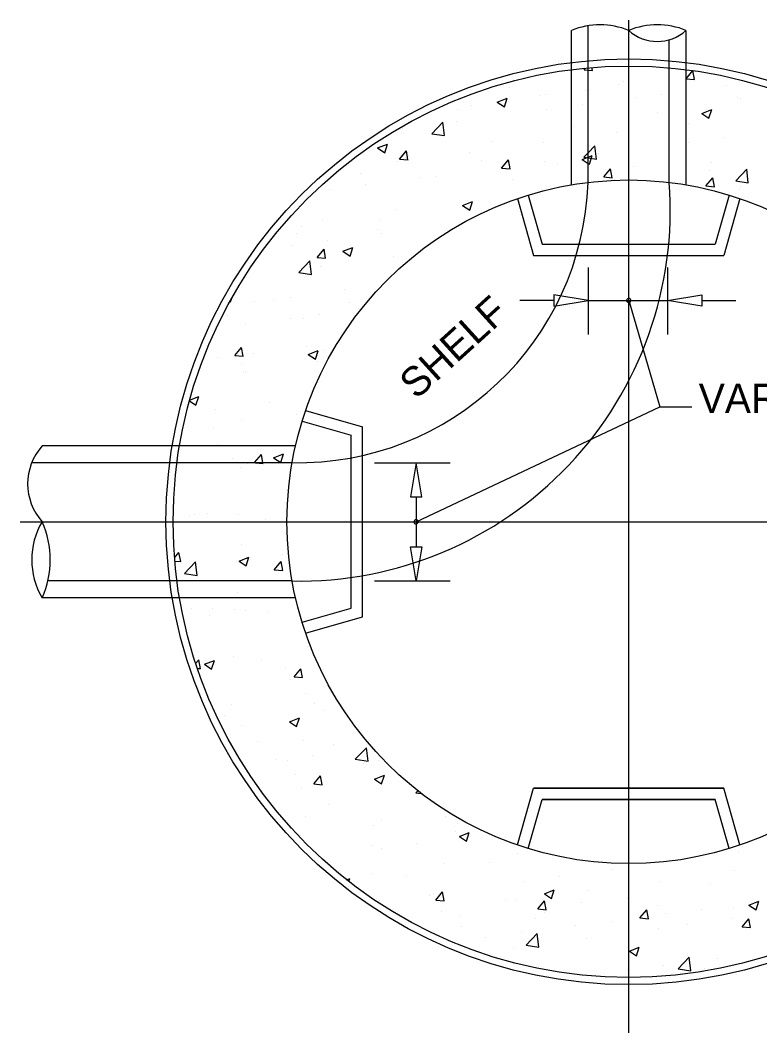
# Model space of a CAD drawing. Extents: x 6712067 to 6713867, y 1867712 to 1869162.
# Drawn here: x 6713498 to 6713649.4, y 1867917.6 to 1868124.8 of the extents above; entities that cross this region are included whole.
import ezdxf

# ---------------------------------------------------------------- set-up
doc = ezdxf.new("R2010")
doc.units = 0
for name, color, linetype in [('G-MARK', 7, 'Continuous'), ('G-TEXT', 7, 'Continuous'), ('Misc CnstDet(22)', 7, 'Continuous')]:
    doc.layers.add(name, color=color, linetype=linetype)

msp = doc.modelspace()

# ---------------------------------------------------------------- linework, layer by layer
at = {"layer": 'G-MARK'}
for p, q in [((6713614.28, 1868074.21), (6713614.28, 1868060.48)), ((6713630.55, 1868074.21), (6713630.55, 1868060.48)), ((6713607.29, 1868067.47), (6713600.29, 1868067.47)), ((6713614.28, 1868067.47), (6713630.55, 1868067.47)), ((6713622.6, 1868067.47), (6713628.98, 1868045.69)), ((6713637.54, 1868067.47), (6713644.54, 1868067.47)), ((6713570.53, 1868034.25), (6713586.06, 1868034.25)), ((6713579.06, 1868027.26), (6713579.06, 1868017.05)), ((6713570.53, 1868010.05), (6713586.06, 1868010.05))]:
    msp.add_line(p, q, dxfattribs=at)
msp.add_lwpolyline([(6713579.06, 1868022.15), (6713628.98, 1868045.69), (6713635.55, 1868045.69)], dxfattribs=at)
at = {"layer": 'G-TEXT'}
for points in [[(6713607.29, 1868068.64), (6713607.29, 1868066.31), (6713614.28, 1868067.47)], [(6713637.54, 1868068.64), (6713637.54, 1868066.31), (6713630.55, 1868067.47)], [(6713577.9, 1868027.26), (6713580.23, 1868027.26), (6713579.06, 1868034.25)], [(6713577.9, 1868017.05), (6713580.23, 1868017.05), (6713579.06, 1868010.05)]]:
    msp.add_lwpolyline(points, close=True, dxfattribs=at)
at = {"layer": 'Misc CnstDet(22)'}
for p, q in [((6713622.6, 1867917.57), (6713622.6, 1868124.81)), ((6713610.86, 1868116.15), (6713610.86, 1868122.72)), ((6713614.28, 1868091.62), (6713614.28, 1868123.68)), ((6713634.33, 1868116.15), (6713634.33, 1868122.72)), ((6713630.91, 1868091.62), (6713630.91, 1868120.8)), ((6713610.86, 1868091.11), (6713610.86, 1868116.26)), ((6713613.45, 1868114.65), (6713613.74, 1868115)), ((6713613.45, 1868114.65), (6713614.28, 1868114.58)), ((6713614.28, 1868114.58), (6713615.19, 1868114.5)), ((6713615.19, 1868114.5), (6713615.08, 1868115.12)), ((6713634.33, 1868091.11), (6713634.33, 1868116.12)), ((6713634.35, 1868112.82), (6713635.75, 1868114.5)), ((6713636.1, 1868112.66), (6713635.75, 1868114.49)), ((6713621.51, 1868112.28), (6713621.51, 1868112.28)), ((6713634.35, 1868112.82), (6713636.1, 1868112.67)), ((6713635.16, 1868113.48), (6713635.16, 1868113.48)), ((6713598.24, 1868111.01), (6713598.24, 1868111.01)), ((6713613.8, 1868110.36), (6713613.8, 1868110.36)), ((6713620.43, 1868111.61), (6713620.43, 1868111.61)), ((6713642.56, 1868111.37), (6713642.56, 1868111.37)), ((6713595.68, 1868108.06), (6713597.72, 1868108.85)), ((6713595.68, 1868108.06), (6713597.14, 1868107.08)), ((6713597.14, 1868107.08), (6713597.72, 1868108.84)), ((6713604.52, 1868109.37), (6713604.52, 1868109.37)), ((6713605.47, 1868109.55), (6713605.47, 1868109.55)), ((6713624.15, 1868108.94), (6713624.15, 1868108.94)), ((6713629.36, 1868109.7), (6713629.36, 1868109.7)), ((6713644.91, 1868109.05), (6713644.91, 1868109.05)), ((6713645.5, 1868108.79), (6713645.5, 1868108.79)), ((6713587.52, 1868106.44), (6713587.52, 1868106.44)), ((6713590.33, 1868107.37), (6713590.33, 1868107.37)), ((6713605.81, 1868106.52), (6713605.81, 1868106.52)), ((6713613.11, 1868107.49), (6713613.11, 1868107.49)), ((6713628.5, 1868105.88), (6713628.5, 1868105.88)), ((6713637.58, 1868105.73), (6713639.62, 1868106.51)), ((6713639.03, 1868104.74), (6713639.62, 1868106.51)), ((6713582.29, 1868101.59), (6713584.56, 1868103.95)), ((6713584.88, 1868101.19), (6713584.56, 1868103.95)), ((6713587.41, 1868104.1), (6713587.41, 1868104.1)), ((6713634.81, 1868103.77), (6713634.81, 1868103.77)), ((6713637.58, 1868105.73), (6713639.03, 1868104.76)), ((6713576.37, 1868102.66), (6713576.37, 1868102.66)), ((6713611.51, 1868102.97), (6713611.51, 1868102.97)), ((6713620.09, 1868101.9), (6713620.09, 1868101.9)), ((6713582.29, 1868101.59), (6713584.88, 1868101.19)), ((6713594.51, 1868100.05), (6713594.51, 1868100.05)), ((6713605.11, 1868099.86), (6713605.11, 1868099.86)), ((6713634.89, 1868099.87), (6713634.89, 1868099.87)), ((6713642.19, 1868100.83), (6713642.19, 1868100.83)), ((6713571.19, 1868098.66), (6713573.23, 1868099.44)), ((6713571.19, 1868098.66), (6713572.65, 1868097.69)), ((6713572.65, 1868097.69), (6713573.23, 1868099.44)), ((6713575.68, 1868096.39), (6713577.08, 1868098.06)), ((6713577.41, 1868096.23), (6713577.08, 1868098.05)), ((6713589.98, 1868097.66), (6713589.98, 1868097.66)), ((6713613.4, 1868096.77), (6713614.28, 1868097.7)), ((6713614.28, 1868097.7), (6713615.67, 1868099.13)), ((6713615.98, 1868096.37), (6713615.66, 1868099.13)), ((6713575.25, 1868095.8), (6713575.25, 1868095.8)), ((6713575.68, 1868096.39), (6713577.42, 1868096.23)), ((6713577, 1868096.78), (6713577, 1868096.78)), ((6713577.5, 1868097.12), (6713577.5, 1868097.12)), ((6713592.56, 1868096.11), (6713592.56, 1868096.11)), ((6713596.59, 1868094.55), (6713597.99, 1868096.23)), ((6713598.32, 1868094.4), (6713597.99, 1868096.23)), ((6713605.45, 1868095.99), (6713605.45, 1868095.99)), ((6713613.09, 1868096.33), (6713614.28, 1868096.79)), ((6713613.09, 1868096.33), (6713614.28, 1868095.52)), ((6713613.4, 1868096.77), (6713614.28, 1868096.63)), ((6713614.28, 1868096.79), (6713615.12, 1868097.11)), ((6713614.28, 1868096.63), (6713615.99, 1868096.37)), ((6713614.28, 1868095.52), (6713614.54, 1868095.35)), ((6713614.54, 1868095.35), (6713615.12, 1868097.11)), ((6713616.49, 1868097.45), (6713616.49, 1868097.45)), ((6713639.63, 1868095.68), (6713639.63, 1868095.68)), ((6713567.59, 1868093.52), (6713567.59, 1868093.52)), ((6713596.59, 1868094.55), (6713598.32, 1868094.4)), ((6713598.15, 1868095.04), (6713598.15, 1868095.04)), ((6713608.12, 1868095.46), (6713608.12, 1868095.46)), ((6713617.49, 1868092.73), (6713618.9, 1868094.4)), ((6713619.23, 1868092.57), (6713618.9, 1868094.4)), ((6713623.68, 1868094.81), (6713623.68, 1868094.81)), ((6713634.46, 1868094.06), (6713634.46, 1868094.06)), ((6713639.24, 1868094.15), (6713639.24, 1868094.15)), ((6713644.5, 1868091.94), (6713646.77, 1868094.31)), ((6713647.09, 1868091.53), (6713646.77, 1868094.3)), ((6713579.74, 1868092.6), (6713579.74, 1868092.6)), ((6713583.15, 1868092.87), (6713583.15, 1868092.87)), ((6713598.71, 1868092.2), (6713598.71, 1868092.2)), ((6713617.49, 1868092.73), (6713619.23, 1868092.58)), ((6713619.73, 1868092.2), (6713619.73, 1868092.2)), ((6713622.64, 1868092.76), (6713622.64, 1868092.76)), ((6713638.39, 1868090.89), (6713639.81, 1868092.57)), ((6713640.14, 1868090.74), (6713639.81, 1868092.57)), ((6713644.5, 1868091.94), (6713647.09, 1868091.53)), ((6713561.4, 1868090.19), (6713561.4, 1868090.19)), ((6713568.7, 1868091.16), (6713568.7, 1868091.16)), ((6713604.77, 1868090.15), (6713604.77, 1868090.15)), ((6713638.39, 1868090.89), (6713640.14, 1868090.74)), ((6713645.38, 1868090.23), (6713645.38, 1868090.23)), ((6713645.56, 1868090.79), (6713645.56, 1868090.79)), ((6713588.59, 1868086.92), (6713590.63, 1868087.71)), ((6713589.62, 1868087.97), (6713589.62, 1868087.97)), ((6713590.05, 1868085.95), (6713590.63, 1868087.71)), ((6713599.81, 1868088.29), (6713603.14, 1868076.66)), ((6713599.81, 1868088.29), (6713603.14, 1868076.66)), ((6713602.04, 1868089.01), (6713604.9, 1868078.99)), ((6713643.16, 1868089.01), (6713640.3, 1868078.99)), ((6713645.38, 1868088.29), (6713642.06, 1868076.66)), ((6713574.9, 1868086.1), (6713574.9, 1868086.1)), ((6713588.59, 1868086.92), (6713590.05, 1868085.95)), ((6713588.63, 1868086.93), (6713588.63, 1868086.93)), ((6713559.93, 1868084.04), (6713559.93, 1868084.04)), ((6713571.64, 1868084.01), (6713571.64, 1868084.01)), ((6713554.64, 1868081.09), (6713554.64, 1868081.09)), ((6713555.64, 1868082.62), (6713555.64, 1868082.62)), ((6713571.2, 1868081.96), (6713571.2, 1868081.96)), ((6713572.07, 1868081.11), (6713572.07, 1868081.11)), ((6713561.03, 1868079.66), (6713561.03, 1868079.66)), ((6713604.9, 1868078.99), (6713640.3, 1868078.99)), ((6713553.74, 1868078.69), (6713553.74, 1868078.69)), ((6713558.81, 1868076.28), (6713560.22, 1868077.96)), ((6713560.55, 1868076.13), (6713560.22, 1868077.96)), ((6713564.1, 1868077.52), (6713566.14, 1868078.31)), ((6713564.1, 1868077.52), (6713565.56, 1868076.55)), ((6713565.56, 1868076.55), (6713566.14, 1868078.3)), ((6713555.04, 1868073.2), (6713557.32, 1868075.56)), ((6713557.64, 1868072.79), (6713557.32, 1868075.56)), ((6713558.81, 1868076.28), (6713560.55, 1868076.13)), ((6713574.54, 1868076.39), (6713574.54, 1868076.39)), ((6713603.14, 1868076.66), (6713642.06, 1868076.66)), ((6713614.28, 1868076.66), (6713614.28, 1868076.66)), ((6713630.55, 1868076.66), (6713630.55, 1868076.66)), ((6713555.04, 1868073.2), (6713557.64, 1868072.79)), ((6713559.58, 1868074.34), (6713559.58, 1868074.34)), ((6713544.44, 1868072.15), (6713544.44, 1868072.15)), ((6713564.4, 1868069.62), (6713564.4, 1868069.62)), ((6713540.94, 1868067.23), (6713541.05, 1868067.15)), ((6713541.05, 1868067.15), (6713541.32, 1868067.91)), ((6713546.06, 1868067.19), (6713546.06, 1868067.19)), ((6713549.96, 1868067.72), (6713549.96, 1868067.72)), ((6713553.36, 1868068.16), (6713553.36, 1868068.16)), ((6713565.52, 1868067.07), (6713565.52, 1868067.07)), ((6713630.55, 1868067.47), (6713630.55, 1868067.47)), ((6713540.55, 1868064.46), (6713540.55, 1868064.46)), ((6713559.22, 1868064.64), (6713559.22, 1868064.64)), ((6713544.08, 1868062.45), (6713544.08, 1868062.45)), ((6713553.44, 1868063.69), (6713553.44, 1868063.69)), ((6713556.11, 1868063.81), (6713556.11, 1868063.81)), ((6713541.95, 1868056.19), (6713543.35, 1868057.86)), ((6713541.95, 1868056.19), (6713543.69, 1868056.04)), ((6713543.69, 1868056.04), (6713543.35, 1868057.86)), ((6713545.69, 1868056.66), (6713545.69, 1868056.66)), ((6713556.73, 1868058.12), (6713556.73, 1868058.12)), ((6713557.01, 1868056.38), (6713559.05, 1868057.18)), ((6713557.01, 1868056.38), (6713558.46, 1868055.41)), ((6713558.46, 1868055.41), (6713559.05, 1868057.16)), ((6713560.41, 1868057.3), (6713560.41, 1868057.3)), ((6713538.39, 1868055.71), (6713538.39, 1868055.71)), ((6713543.42, 1868054.39), (6713543.42, 1868054.39)), ((6713558.88, 1868054.93), (6713558.88, 1868054.93)), ((6713543.73, 1868052.75), (6713543.73, 1868052.75)), ((6713544.16, 1868052.91), (6713544.16, 1868052.91)), ((6713532.67, 1868046.89), (6713533.96, 1868046.01)), ((6713532.71, 1868047.07), (6713534.56, 1868047.77)), ((6713533.96, 1868046.01), (6713534.56, 1868047.77)), ((6713549.07, 1868046.62), (6713549.07, 1868046.62)), ((6713538.03, 1868045.17), (6713538.03, 1868045.17)), ((6713554.55, 1868044.18), (6713554.55, 1868044.18)), ((6713556.46, 1868044.93), (6713568.09, 1868041.6)), ((6713543.37, 1868043.05), (6713543.37, 1868043.05)), ((6713555.73, 1868042.72), (6713565.76, 1868039.85)), ((6713568.09, 1868002.69), (6713568.09, 1868041.6)), ((6713537.55, 1868041.26), (6713537.55, 1868041.26)), ((6713565.76, 1868004.46), (6713565.76, 1868039.85)), ((6713529.14, 1868037.68), (6713502.5, 1868037.68)), ((6713554.39, 1868037.68), (6713529.14, 1868037.68)), ((6713538.48, 1868038.01), (6713538.48, 1868038.01)), ((6713545.99, 1868034.27), (6713547.4, 1868035.95)), ((6713547.71, 1868034.25), (6713547.4, 1868035.93)), ((6713549.91, 1868035.25), (6713551.96, 1868036.04)), ((6713551.36, 1868034.27), (6713551.96, 1868036.04)), ((6713554.05, 1868037.36), (6713554.05, 1868037.36)), ((6713553.69, 1868034.25), (6713500.38, 1868034.25)), ((6713530.36, 1868033.67), (6713530.36, 1868033.67)), ((6713541.4, 1868035.12), (6713541.4, 1868035.12)), ((6713543.03, 1868033.34), (6713543.03, 1868033.34)), ((6713544.64, 1868034.1), (6713544.64, 1868034.1)), ((6713545.99, 1868034.27), (6713546.17, 1868034.25)), ((6713546.17, 1868034.25), (6713547.73, 1868034.11)), ((6713547.73, 1868034.11), (6713547.71, 1868034.25)), ((6713549.91, 1868035.25), (6713551.37, 1868034.27)), ((6713568.09, 1868034.25), (6713568.09, 1868034.25)), ((6713552.14, 1868026.05), (6713552.14, 1868026.05)), ((6713532.69, 1868023.2), (6713532.69, 1868023.2)), ((6713533.73, 1868023.63), (6713533.73, 1868023.63)), ((6713536.35, 1868023.87), (6713536.35, 1868023.87)), ((6713542.67, 1868023.63), (6713542.67, 1868023.63)), ((6713498.03, 1868022.15), (6713728.02, 1868022.15)), ((6713548.25, 1868022.54), (6713548.25, 1868022.54)), ((6713543.34, 1868017.47), (6713543.34, 1868017.47)), ((6713529.61, 1868014.75), (6713530.53, 1868015.84)), ((6713530.88, 1868014.01), (6713530.53, 1868015.84)), ((6713542.82, 1868014.12), (6713544.86, 1868014.9)), ((6713544.27, 1868013.13), (6713544.86, 1868014.9)), ((6713551.76, 1868015.52), (6713551.76, 1868015.52)), ((6713529.67, 1868014.12), (6713530.88, 1868014.01)), ((6713531.67, 1868011.58), (6713533.93, 1868013.95)), ((6713534.25, 1868011.18), (6713533.93, 1868013.95)), ((6713542.32, 1868013.93), (6713542.32, 1868013.93)), ((6713542.82, 1868014.12), (6713544.28, 1868013.13)), ((6713544.46, 1868014.55), (6713544.46, 1868014.55)), ((6713550.04, 1868012.34), (6713551.44, 1868014.01)), ((6713551.77, 1868012.19), (6713551.44, 1868014.01)), ((6713531.67, 1868011.58), (6713534.25, 1868011.18)), ((6713550.04, 1868012.34), (6713551.78, 1868012.19)), ((6713553.69, 1868010.04), (6713503.67, 1868010.04)), ((6713568.09, 1868010.05), (6713568.09, 1868010.05)), ((6713579.06, 1868010.05), (6713579.06, 1868010.05)), ((6713529.14, 1868006.62), (6713502.5, 1868006.62)), ((6713554.39, 1868006.62), (6713529.14, 1868006.62)), ((6713542.57, 1868007.65), (6713542.57, 1868007.65)), ((6713533.16, 1868004.39), (6713533.16, 1868004.39)), ((6713537.46, 1868004.35), (6713537.46, 1868004.35)), ((6713555.73, 1868001.59), (6713565.76, 1868004.46)), ((6713536.8, 1868003.06), (6713536.8, 1868003.06)), ((6713541.96, 1868004.23), (6713541.96, 1868004.23)), ((6713544.1, 1868004.02), (6713544.1, 1868004.02)), ((6713548.72, 1868003.72), (6713548.72, 1868003.72)), ((6713556.46, 1867999.36), (6713568.09, 1868002.69)), ((6713556.74, 1867996.71), (6713556.74, 1867996.71)), ((6713541.61, 1867994.53), (6713541.61, 1867994.53)), ((6713547.47, 1867993.98), (6713547.47, 1867993.98)), ((6713533.94, 1867993.16), (6713534.58, 1867993.92)), ((6713534.27, 1867992.15), (6713534.92, 1867992.1)), ((6713534.92, 1867992.08), (6713534.58, 1867993.92)), ((6713535.73, 1867992.98), (6713537.77, 1867993.76)), ((6713535.73, 1867992.98), (6713537.19, 1867992)), ((6713536.43, 1867992.52), (6713536.43, 1867992.52)), ((6713536.77, 1867992.83), (6713536.77, 1867992.83)), ((6713537.18, 1867991.99), (6713537.77, 1867993.76)), ((6713552.34, 1867992.16), (6713552.34, 1867992.16)), ((6713554.08, 1867990.42), (6713555.49, 1867992.08)), ((6713555.82, 1867990.26), (6713555.49, 1867992.08)), ((6713553.27, 1867989.88), (6713553.27, 1867989.88)), ((6713554.08, 1867990.42), (6713555.82, 1867990.26)), ((6713536.27, 1867986.95), (6713536.27, 1867986.95)), ((6713556.39, 1867987.01), (6713556.39, 1867987.01)), ((6713541.25, 1867984.82), (6713541.25, 1867984.82)), ((6713558.21, 1867984.9), (6713558.21, 1867984.9)), ((6713539.8, 1867982.48), (6713539.8, 1867982.48)), ((6713553.13, 1867981.24), (6713555.17, 1867982.02)), ((6713554.59, 1867980.26), (6713555.17, 1867982.02)), ((6713560.24, 1867983.48), (6713560.24, 1867983.48)), ((6713543.25, 1867980.56), (6713543.25, 1867980.56)), ((6713553.13, 1867981.24), (6713554.59, 1867980.26)), ((6713546.66, 1867977.27), (6713546.66, 1867977.27)), ((6713556.03, 1867977.3), (6713556.03, 1867977.3)), ((6713562.22, 1867976.61), (6713562.22, 1867976.61)), ((6713566.63, 1867973.54), (6713568.91, 1867975.9)), ((6713568.88, 1867975.82), (6713568.88, 1867975.82)), ((6713569.23, 1867973.14), (6713568.91, 1867975.9)), ((6713550.55, 1867973.4), (6713550.55, 1867973.4)), ((6713552.81, 1867973.36), (6713552.81, 1867973.36)), ((6713557.84, 1867974.37), (6713557.84, 1867974.37)), ((6713566.63, 1867973.54), (6713569.23, 1867973.14)), ((6713571.39, 1867973.27), (6713571.39, 1867973.27)), ((6713568.37, 1867972.7), (6713568.37, 1867972.7)), ((6713554.38, 1867970.36), (6713554.38, 1867970.36)), ((6713558.13, 1867968.49), (6713559.53, 1867970.16)), ((6713559.86, 1867968.33), (6713559.53, 1867970.16)), ((6713570.53, 1867969.5), (6713572.57, 1867970.29)), ((6713570.53, 1867969.5), (6713571.98, 1867968.52)), ((6713570.65, 1867969.65), (6713570.65, 1867969.65)), ((6713571.98, 1867968.52), (6713572.57, 1867970.28)), ((6713555.69, 1867967.61), (6713555.69, 1867967.61)), ((6713558.13, 1867968.49), (6713559.86, 1867968.34)), ((6713579.03, 1867966.66), (6713579.41, 1867967.11)), ((6713599.81, 1867956), (6713603.14, 1867967.64)), ((6713599.81, 1867956), (6713603.14, 1867967.64)), ((6713603.14, 1867967.64), (6713642.06, 1867967.64)), ((6713642.06, 1867967.64), (6713603.14, 1867967.64)), ((6713645.38, 1867956), (6713642.06, 1867967.64)), ((6713645.38, 1867956), (6713642.06, 1867967.64)), ((6713579.03, 1867966.66), (6713580.12, 1867966.56)), ((6713579.61, 1867966.74), (6713579.61, 1867966.74)), ((6713602.04, 1867955.28), (6713604.9, 1867965.31)), ((6713602.04, 1867955.28), (6713604.9, 1867965.31)), ((6713604.9, 1867965.31), (6713640.3, 1867965.31)), ((6713640.3, 1867965.31), (6713604.9, 1867965.31)), ((6713643.16, 1867955.28), (6713640.3, 1867965.31)), ((6713643.16, 1867955.28), (6713640.3, 1867965.31)), ((6713561.21, 1867964.32), (6713561.21, 1867964.32)), ((6713556.42, 1867961.8), (6713556.42, 1867961.8)), ((6713571.98, 1867961.14), (6713571.98, 1867961.14)), ((6713585.02, 1867961.81), (6713585.02, 1867961.81)), ((6713570.3, 1867959.95), (6713570.3, 1867959.95)), ((6713587.18, 1867958.8), (6713587.18, 1867958.8)), ((6713587.54, 1867960.48), (6713587.54, 1867960.48)), ((6713555.33, 1867957.9), (6713555.33, 1867957.9)), ((6713587.93, 1867957.77), (6713589.97, 1867958.55)), ((6713587.93, 1867957.77), (6713589.38, 1867956.8)), ((6713589.38, 1867956.78), (6713589.97, 1867958.55)), ((6713590.29, 1867957.67), (6713590.29, 1867957.67)), ((6713570.18, 1867955.89), (6713570.18, 1867955.89)), ((6713571.95, 1867955.25), (6713571.95, 1867955.25)), ((6713579.25, 1867956.21), (6713579.25, 1867956.21)), ((6713599.8, 1867954.29), (6713599.8, 1867954.29)), ((6713637.77, 1867953.43), (6713637.77, 1867953.43)), ((6713645.07, 1867954.39), (6713645.07, 1867954.39)), ((6713584.66, 1867952.11), (6713584.66, 1867952.11)), ((6713594.17, 1867952.4), (6713594.17, 1867952.4)), ((6713619.37, 1867951), (6713619.37, 1867951)), ((6713644.28, 1867950.7), (6713644.28, 1867950.7)), ((6713564.84, 1867948.9), (6713565.48, 1867949.15)), ((6713565.28, 1867948.56), (6713565.48, 1867949.15)), ((6713569.94, 1867950.24), (6713569.94, 1867950.24)), ((6713577.16, 1867949.49), (6713577.16, 1867949.49)), ((6713601.03, 1867948.59), (6713601.03, 1867948.59)), ((6713608.33, 1867949.55), (6713608.33, 1867949.55)), ((6713629.13, 1867948.51), (6713629.13, 1867948.51)), ((6713583.08, 1867944.73), (6713584.48, 1867946.41)), ((6713584.82, 1867944.58), (6713584.48, 1867946.41)), ((6713605.33, 1867946.03), (6713607.37, 1867946.81)), ((6713606.78, 1867945.06), (6713607.37, 1867946.81)), ((6713614.41, 1867946.65), (6713614.41, 1867946.65)), ((6713639.29, 1867948.04), (6713639.29, 1867948.04)), ((6713571.58, 1867944.71), (6713571.58, 1867944.71)), ((6713581.86, 1867945.58), (6713581.86, 1867945.58)), ((6713582.62, 1867946.17), (6713582.62, 1867946.17)), ((6713583.08, 1867944.73), (6713584.82, 1867944.58)), ((6713597.42, 1867944.93), (6713597.42, 1867944.93)), ((6713599.44, 1867944.6), (6713599.44, 1867944.6)), ((6713603.99, 1867942.91), (6713605.39, 1867944.58)), ((6713605.33, 1867946.03), (6713606.78, 1867945.06)), ((6713605.72, 1867942.75), (6713605.39, 1867944.57)), ((6713612.99, 1867944.27), (6713612.99, 1867944.27)), ((6713622.29, 1867945.12), (6713622.29, 1867945.12)), ((6713647.22, 1867943.7), (6713649.26, 1867944.48)), ((6713648.45, 1867944.34), (6713648.45, 1867944.34)), ((6713648.67, 1867942.71), (6713649.26, 1867944.48)), ((6713584.31, 1867942.4), (6713584.31, 1867942.4)), ((6713603.99, 1867942.91), (6713605.73, 1867942.75)), ((6713605.3, 1867942.2), (6713605.3, 1867942.2)), ((6713624.9, 1867941.07), (6713626.3, 1867942.75)), ((6713626.63, 1867940.92), (6713626.3, 1867942.75)), ((6713628.55, 1867943.62), (6713628.55, 1867943.62)), ((6713637.41, 1867942.89), (6713637.41, 1867942.89)), ((6713644.11, 1867942.96), (6713644.11, 1867942.96)), ((6713647.22, 1867943.7), (6713648.67, 1867942.71)), ((6713588.01, 1867941.67), (6713588.01, 1867941.67)), ((6713603.56, 1867941.02), (6713603.56, 1867941.02)), ((6713619.13, 1867940.36), (6713619.13, 1867940.36)), ((6713624.9, 1867941.07), (6713626.63, 1867940.92)), ((6713630.11, 1867941.93), (6713630.11, 1867941.93)), ((6713643.93, 1867940.99), (6713643.93, 1867940.99)), ((6713645.8, 1867939.25), (6713647.21, 1867940.92)), ((6713647.54, 1867939.09), (6713647.21, 1867940.92)), ((6713588.29, 1867939.28), (6713588.29, 1867939.28)), ((6713600.66, 1867938.05), (6713600.66, 1867938.05)), ((6713611.7, 1867939.51), (6713611.7, 1867939.51)), ((6713628.78, 1867938.81), (6713628.78, 1867938.81)), ((6713634.69, 1867939.7), (6713634.69, 1867939.7)), ((6713645.8, 1867939.25), (6713647.54, 1867939.1)), ((6713593.36, 1867937.09), (6713593.36, 1867937.09)), ((6713601.61, 1867935.5), (6713603.87, 1867937.86)), ((6713604.2, 1867935.09), (6713603.87, 1867937.86)), ((6713614.05, 1867936.94), (6713614.05, 1867936.94)), ((6713599.09, 1867934.89), (6713599.09, 1867934.89)), ((6713601.61, 1867935.5), (6713604.21, 1867935.09)), ((6713622.73, 1867934.29), (6713624.77, 1867935.08)), ((6713622.73, 1867934.29), (6713624.18, 1867933.32)), ((6713624.18, 1867933.32), (6713624.77, 1867935.08)), ((6713632.71, 1867930.66), (6713634.99, 1867933.04)), ((6713635.31, 1867930.26), (6713634.99, 1867933.03)), ((6713640.77, 1867932.84), (6713640.77, 1867932.84)), ((6713622.44, 1867930.43), (6713622.44, 1867930.43)), ((6713629.73, 1867931.4), (6713629.73, 1867931.4)), ((6713632.71, 1867930.66), (6713635.31, 1867930.26)), ((6713638.08, 1867930.64), (6713638.08, 1867930.64)), ((6713643.57, 1867931.3), (6713643.57, 1867931.3)), ((6713628.43, 1867929.1), (6713628.43, 1867929.1))]:
    msp.add_line(p, q, dxfattribs=at)
for radius in [94.73, 93.28, 69.96]:
    msp.add_circle((6713622.6, 1868022.15), radius, dxfattribs=at)
for centre, radius, start, end in [((6713616.73, 1868108.53), 15.35, 67.5261, 112.4739), ((6713628.46, 1868108.53), 15.35, 67.5261, 112.4739), ((6713628.46, 1868129.21), 8.75, 227.8917, 312.1083), ((6713554.91, 1868093.65), 59.41, 268.8322, 358.0303), ((6713555.2, 1868085.95), 75.92, 268.8614, 4.2761), ((6713622.6, 1868067.47), 0.437, 106.3408, 286.3408), ((6713622.6, 1868067.47), 0.437, 286.3408, 106.3408), ((6713511.26, 1868029.91), 11.71, 138.4565, 221.5435), ((6713515.7, 1868014.38), 15.32, 149.5444, 210.4556), ((6713485.36, 1868014.38), 18.82, 335.6342, 24.3658), ((6713579.06, 1868022.15), 0.437, 25.2454, 205.2454), ((6713579.06, 1868022.15), 0.437, 205.2454, 25.2454)]:
    msp.add_arc(centre, radius, start, end, dxfattribs=at)

# ---------------------------------------------------------------- texts
msp.add_text('SHELF', height=6, rotation=42.2637, dxfattribs=at).set_placement((6713579.12, 1868047.03))
msp.add_text('VARIABLE', height=6, dxfattribs=at).set_placement((6713636.93, 1868044.41))

doc.saveas('drawing.dxf')
